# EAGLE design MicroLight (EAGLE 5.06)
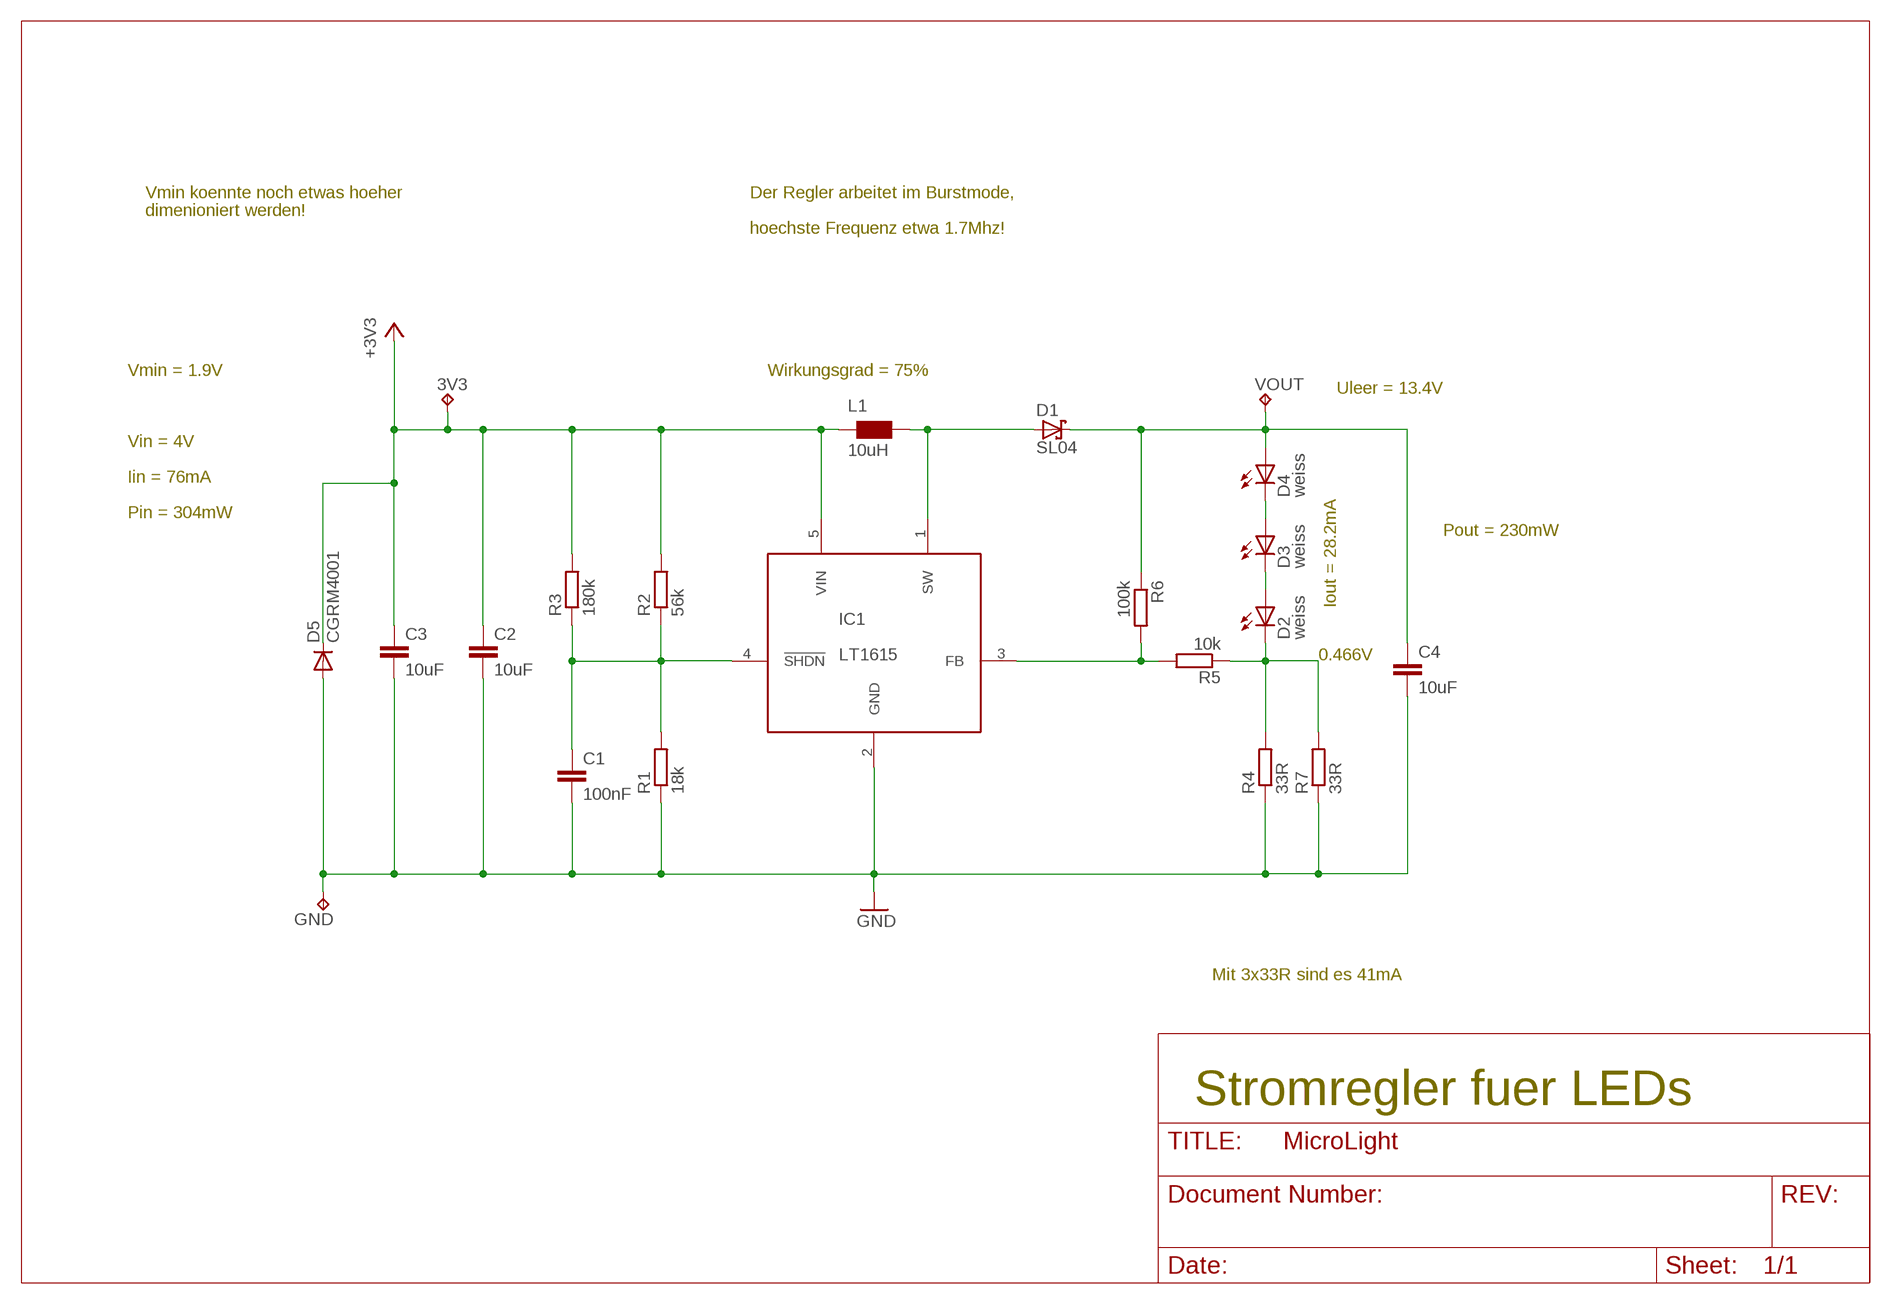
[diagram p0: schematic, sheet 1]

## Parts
3V3  TPPAD1-13  [P1-13]
C1  100nF  C-EUC0603  [C0603]
C2  10uF  C-EUC0805  [C0805]
C3  10uF  C-EUC0805  [C0805]
C4  10uF  C-EUC1210  [C1210]
D1  SL04  [DO219]
D2  weiss  LED_KAI  [LED_KAI]
D3  weiss  LED_KAI  [LED_KAI]
D4  weiss  LED_KAI  [LED_KAI]
D5  CGRM4001  CGRM4001-G  [SOD-123_MINI-SMA]
GND  TPPAD1-13  [P1-13]
IC1  LT1615  [SOT23-5]
L1  10uH  WE-PD_S/M  [WE-PD_S/M]
R1  18k  R-EU_R0603  [R0603]
R2  56k  R-EU_R0603  [R0603]
R3  180k  R-EU_R0603  [R0603]
R4  33R  R-EU_R0603  [R0603]
R5  10k  R-EU_R0603  [R0603]
R6  100k  R-EU_R0603  [R0603]
R7  33R  R-EU_R0603  [R0603]
VOUT  TPB2,54  [B2,54]

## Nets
+3V3: 3V3.1(TP) C2.1 C3.1 D5.C IC1.5(VIN) L1.2 R2.2 R3.2
GND: C1.2 C2.2 C3.2 C4.2 D5.A GND.1(TP) IC1.2(GND) R1.1 R4.1 R7.1
N$2: IC1.3(FB) R5.2 R6.2
N$3: D2.K(C) R4.2 R5.1 R7.2
N$4: C4.1 D1.K(C) D4.A R6.1 VOUT.PP(TP)
N$5: D1.A IC1.1(SW) L1.1
N$6: C1.1 IC1.4(!SHDN) R1.2 R2.1 R3.1
N$7: D3.A D4.K(C)
N$9: D2.A D3.K(C)

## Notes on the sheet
- Vmin koennte noch etwas hoeher | Der Regler arbeitet im Burstmode,
- dimenioniert werden!
- hoechste Frequenz etwa 1.7Mhz!
- Vmin = 1.9V | Wirkungsgrad = 75%
- Uleer = 13.4V
- Vin = 4V
- Iin = 76mA
- Pin = 304mW
- Pout = 230mW
- Iout = 28.2mA
- 0.466V
- Mit 3x33R sind es 41mA
- Stromregler fuer LEDs

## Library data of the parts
3V3 GND VOUT = testpad:TP: Test pad
C1-C4 = rcl:C-EU: CAPACITOR, European symbol
D1 = olaf_V5:SL04: Shottky 40V/1A
D2-D4 = olaf_V5:LED_KAI: Weisse LED von Kai, bereits ab 1mA deutlich sichtbar.
D5 = diode:CGRM400*-G: Molded plasitc,JEDEC SOD-123/Mini SMA
IC1 = olaf_V5:LT1615: Micropower Step-Up/Boost Converter. oder Sepic. Funktioniert mit 1V bis 34V eingangsspannung.
L1 = wuerth-elektronik:WE-PD: SMD-Shielded Power Inductors WE-PD
R1-R7 = rcl:R-EU_: RESISTOR, European symbol

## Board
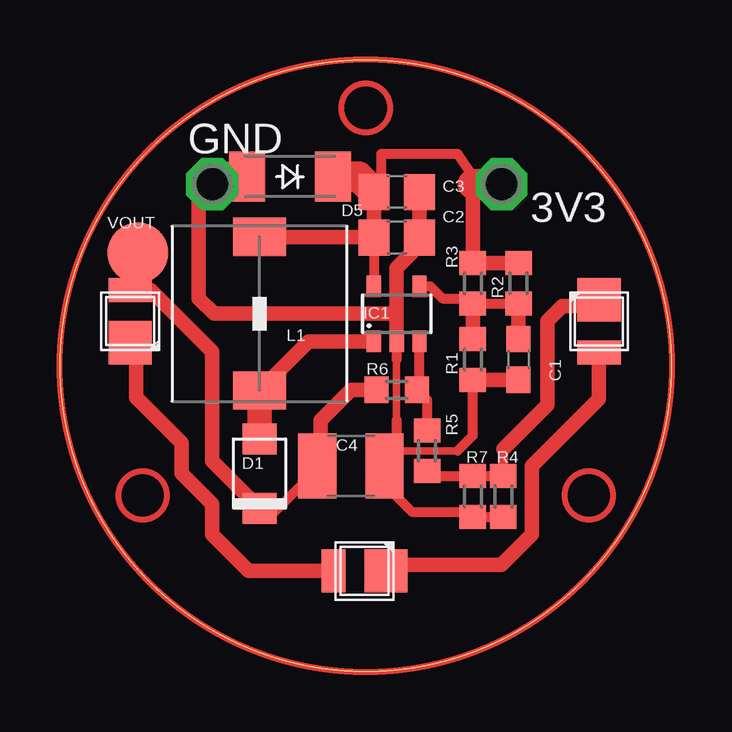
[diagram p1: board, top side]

Size 25.5 x 25.5 mm. Coordinates in mm from the lower left corner, seen from the top.
Outline: circle at 12.75,12.75 radius 12.75
Copper layers (1*16): Top 0.035mm / dielectric 1.5mm / Bottom 0.035mm
Design rules "default": minimum track width 10mil, minimum drill 24mil, track to track 8mil, track to pad 8mil, pad to pad 8mil, via to via 8mil, smd to smd 8mil, copper to edge 40mil, drill to drill 8mil, minimum pad ring 10mil, minimum via ring 8mil, stop-mask expansion 4mil, vias tented up to drill 0mil, thermal gap 10mil

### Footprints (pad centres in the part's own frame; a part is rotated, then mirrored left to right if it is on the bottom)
P1-13 = drill 1.321 pad 2.159 octagon: 1 0,0
C0603 = smd 1.1 x 1: 1 -0.85,0; 2 0.85,0
C0805 = smd 1.3 x 1.5: 1 -0.95,0; 2 0.95,0
C1210 = smd 1.6 x 2.7: 1 -1.4,0; 2 1.4,0
DO219 = smd 1.3 x 1.4: A 1.45,0; K -1.45,0
LED_KAI = smd 1.8 x 1: A 1.2,-0.1 | smd 1.8 x 1.8: K 1.2,2.1
SOD-123_MINI-SMA = smd 1.5 x 2.1: A 1.8,0; C -1.8,0
SOT23-5 = smd 0.6 x 0.9: 1 -0.95,-1.15; 2 0,-1.15; 3 0.95,-1.15; 4 0.95,1.15; 5 -0.95,1.15
WE-PD_S/M = smd 1.6 x 2.2: 1 -3.2,0; 2 3.2,0
R0603 = smd 1 x 1.1: 1 -0.85,0; 2 0.85,0
B2,54 = smd 2.54 x 2.54: PP 0,0

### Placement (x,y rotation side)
3V3  18.41,20.32 0 top
C1  19.12,13.02 270 top
C2  14.04,18.09 0 top
C3  14.04,20 0 top
C4  12.13,8.57 0 top
D1  8.32,8.25 90 top
D2  21.27,13.4 0 top
D3  11.5,5.39 270 top
D4  4.12,15.81 180 top
D5  9.59,20.64 180 top
GND  6.35,20.32 0 top
IC1  14.04,14.92 0 top
L1  8.32,14.92 90 top
R1  17.21,13.02 90 top
R2  19.12,16.19 90 top
R3  17.21,16.19 90 top
R4  18.48,7.3 90 top
R5  15.31,9.21 90 top
R6  14.04,11.74 0 top
R7  17.21,7.3 90 top
VOUT  3.24,17.46 0 top

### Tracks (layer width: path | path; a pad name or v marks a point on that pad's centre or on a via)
+3V3
  Top 0.406: IC1.5 C2.1 13.09,18.12 | 17.21,20.32 17.21,20.64 16.58,21.59 13.4,21.59 13.4,20.32 C3.1
  Top 0.61: C2.1 C3.1 | L1.2 13.09,18.12 | 17.21,20.32 R3.2 R2.2
  Top 1.27: D5.C 12.45,20.64 C3.1 | 17.21,20.32 3V3.1
GND
  Top 0.305: 14.04,13.02 14.04,10.47 | 14.04,9.21 16.58,9.21
  Top 0.406: 14.67,17.46 14.67,17.78 C2.2 | IC1.2 14.04,13.02 | 14.04,10.47 14.04,9.21 14.04,9.07 C4.2 13.82,8.28 13.82,7.51 14.67,6.67 17,6.67 R7.1 R4.1 | R1.1 17.21,9.84 16.58,9.21 | 5.78,20.25 GND.1 6.03,20.64
  Top 0.61: C2.2 C3.2 | 14.04,14.92 IC1.2 | 14.04,14.92 14.04,16.82 14.67,17.46 | R1.1 C1.2 | 14.04,14.92 6.42,14.92 5.78,15.55 5.78,20.25
  Top 1.27: 6.03,20.64 D5.A
N$2
  Top 0.406: IC1.3 14.99,11.85 R6.2 15.31,11.32 R5.2
N$3
  Top 0.406: R5.1 15.52,8.14 R7.2 R4.2 18.48,9.28 | 22.21,15.24 D2.K
  Top 0.61: 18.48,9.28 20.32,11.11 20.32,14.61 20.95,15.24 22.21,15.24
N$4
  Top 0.406: 10.86,8.7 C4.1 10.73,8.44 8.96,6.67 8.5,6.67 D1.K | 3.78,15.91 D4.A 3.24,16.23
  Top 0.61: R6.1 12.13,11.74 10.86,10.47 10.86,8.7 | 3.78,15.91 6.35,13.34 6.35,8.78 D1.K | VOUT.PP 3.24,16.23
N$5
  Top 0.61: IC1.1 10.37,13.77 L1.1
  Top 1.016: D1.A L1.1
N$6
  Top 0.406: IC1.4 15.43,16.07 15.94,15.55 17,15.55 R3.1 R2.1
  Top 0.61: R2.1 C1.1 | R3.1 R1.2
N$7
  Top 0.406: 3.17,13.46 D4.K
  Top 0.61: D3.A 7.87,4.2 6.35,5.71 6.35,6.99 5.08,8.26 5.08,9.53 3.17,11.43 3.17,13.46
N$9
  Top 0.406: 13.85,4.45 D3.K
  Top 0.61: D2.A 22.48,11.36 19.68,8.57 19.68,5.71 18.41,4.45 13.85,4.45
(copper drawn outside any net)
  shapes: Top circle x4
